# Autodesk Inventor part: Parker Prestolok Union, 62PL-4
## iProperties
Shininess: 20.0
Length Units: 11272
Angle Units: 11279
Time Units: 11290
Mass Units: 11286
Length Display Precision: 3
Angle Display Precision: 2
Created: 2001-09
Part Number: Parker Prestolok Union, 62PL-4
Material: Stainless Steel, Austenitic
Description: Parker Prestolok Union, 62PL-4
Document SubType Name: Modeling
Designer: jhagarty
Density: 0.0
Volumn: 0.0
Area: 0.0
PropertySet Name: Model Information
Control State: 0
Master: False
Checked Out: False
Author: jhagarty
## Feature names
1. Extrusion1
2. Revolution6
3. Mirror3
4. Hole5
